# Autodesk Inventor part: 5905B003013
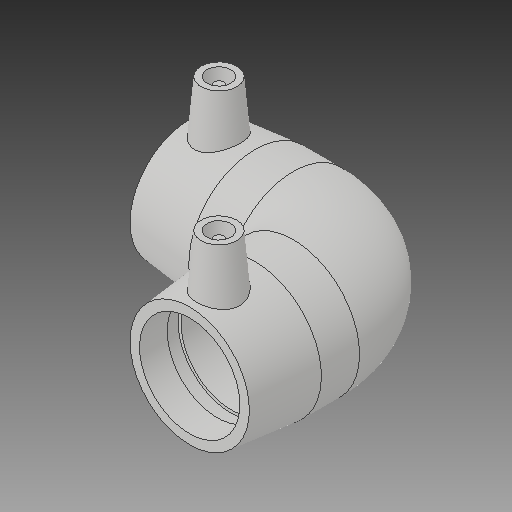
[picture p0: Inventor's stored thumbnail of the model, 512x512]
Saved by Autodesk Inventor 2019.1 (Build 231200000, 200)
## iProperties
Created: 2017-06
Part Number: 5905B003013
Material: Generic
Description: PLASSON 90° ELBOW ASTM 1 1/4''
Document SubType Name: Modeling
Designer: KIM
Mass: 55.0731 g
Surface Area: 148.067 cm^2
Volume: 55.0731 cm^3
Density: 1 g/cm^3
Appearance: Default
Author: KIM
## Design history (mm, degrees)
derived "5905B.ipt"
feature "Solid1::5905B.ipt"
tag "TaggingFeature1"
body "Solid1"
other parameters: "d_" = 42.1, "L_" = 93.218, "L_1" = 43.434, "D_" = 55.626, "A_" = 46.736, "d2" = 55.626, "d4" = 27.41706, "d5" = 50.0634, "d8" = 168 deg, "d10" = 17.3736, "d11" = 5.7912, "d14" = 17.6296, "d18" = 42.1, "d19" = 3.52592, "d20" = 168 deg, "d22" = 51.17592, "d23" = 55.626, "d24" = 49.64064, "d29" = 46.736, "d30" = 15, "d31" = 55.9308, "d34" = 5 deg, "d35" = 15, "d39" = 5 deg, "d41" = 4, "d42" = 14, "d43" = 0, "d45" = 4, "d46" = 14, "d47" = 0, "d49" = 42.1, "d50" = 35.785, "d51" = 17.3736, "d52" = 43.434, "d54" = 90 deg, "d65" = 42.1, "d67" = 45 deg, "d71" = 90 deg, "d75" = 2.7813, "d82" = 45 deg, "d83" = 43.434, "d84" = 50.0634, "d86" = 25.0317, "d87" = 90 deg, "d90" = 43.434, "d91" = 0, "d92" = 43.434, "d93" = 0, "d94" = 90 deg, "d95" = 25.58796, "d98" = 93.218, "d101" = 3, "d102" = 0, "d103" = 3, "d104" = 0, "d105" = 12.59586, "d106" = 3.14896, "d107" = 93.218, "d110" = 23.8887
